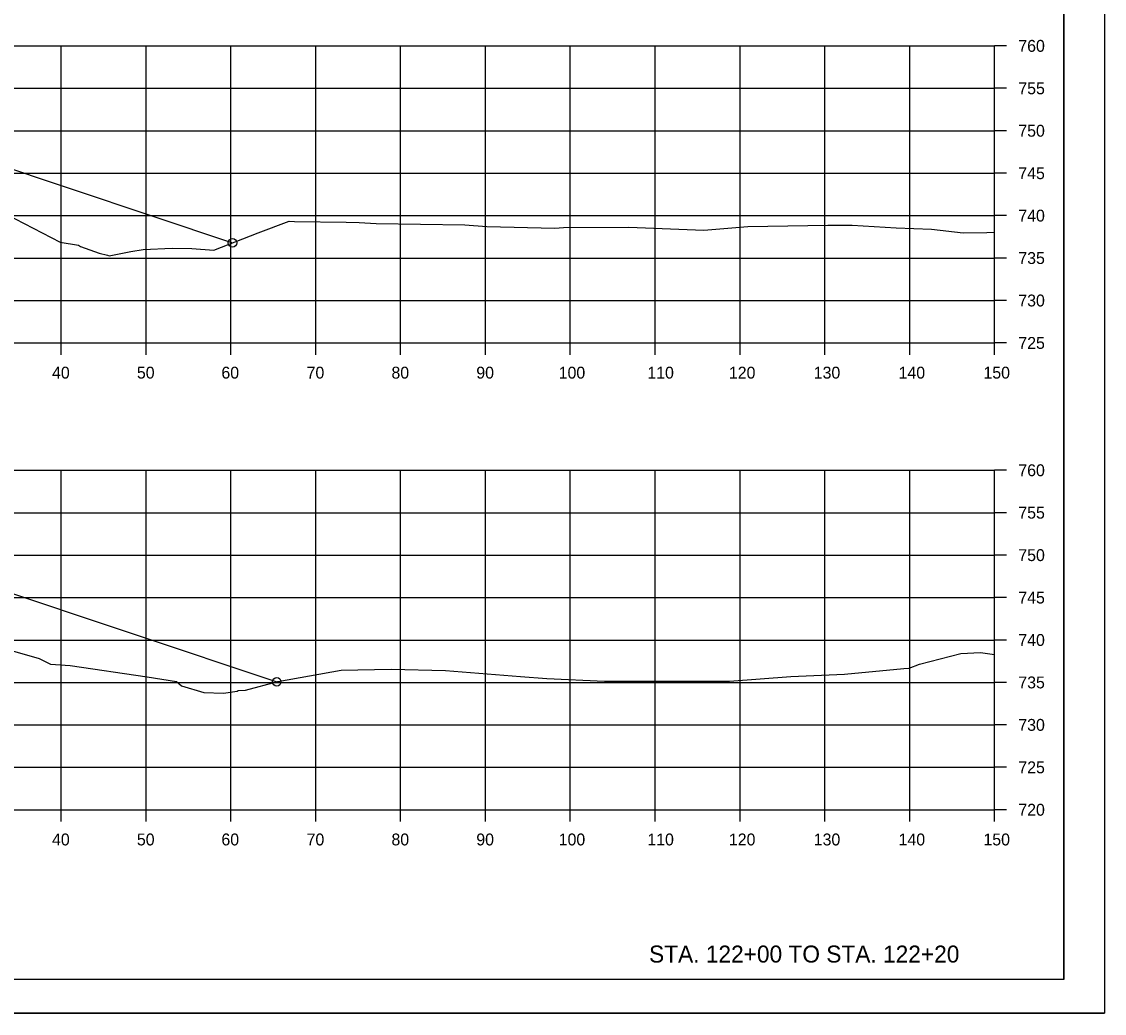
# Model space of a CAD drawing. Extents: x 1202951 to 1376887, y 378065 to 728038.
# Drawn here: x 1373132.5 to 1373260.1, y 381162.4 to 381279.3 of the extents above; entities that cross this region are included whole.
import ezdxf

# ---------------------------------------------------------------- set-up
doc = ezdxf.new("R2010")
doc.units = 0
for name, color, linetype in [('R_Axis', 7, 'Continuous'), ('R_Axis Annot', 7, 'Continuous'), ('R_Draft', 7, 'Continuous'), ('R_Exist Surface', 7, 'Continuous'), ('R_Grid', 7, 'Continuous'), ('R_No Plot', 7, 'Continuous')]:
    doc.layers.add(name, color=color, linetype=linetype)

msp = doc.modelspace()

# ---------------------------------------------------------------- linework, layer by layer
at = {"layer": 'R_Axis'}
for p, q in [((1373247.13, 381241.42), (1373247.13, 381276.42)), ((1373248.53, 381276.42), (1373247.13, 381276.42)), ((1373248.53, 381271.42), (1373247.13, 381271.42)), ((1373248.53, 381266.42), (1373247.13, 381266.42)), ((1373248.53, 381261.42), (1373247.13, 381261.42)), ((1373248.53, 381256.42), (1373247.13, 381256.42)), ((1373248.53, 381251.42), (1373247.13, 381251.42)), ((1373248.53, 381246.42), (1373247.13, 381246.42)), ((1372947.13, 381241.42), (1373247.13, 381241.42)), ((1373137.13, 381240.02), (1373137.13, 381241.42)), ((1373147.13, 381240.02), (1373147.13, 381241.42)), ((1373157.13, 381240.02), (1373157.13, 381241.42)), ((1373167.13, 381240.02), (1373167.13, 381241.42)), ((1373177.13, 381240.02), (1373177.13, 381241.42)), ((1373187.13, 381240.02), (1373187.13, 381241.42)), ((1373197.13, 381240.02), (1373197.13, 381241.42)), ((1373207.13, 381240.02), (1373207.13, 381241.42)), ((1373217.13, 381240.02), (1373217.13, 381241.42)), ((1373227.13, 381240.02), (1373227.13, 381241.42)), ((1373237.13, 381240.02), (1373237.13, 381241.42)), ((1373247.13, 381240.02), (1373247.13, 381241.42)), ((1373248.53, 381241.42), (1373247.13, 381241.42)), ((1373247.13, 381186.42), (1373247.13, 381226.42)), ((1373248.53, 381226.42), (1373247.13, 381226.42)), ((1373248.53, 381221.42), (1373247.13, 381221.42)), ((1373248.53, 381216.42), (1373247.13, 381216.42)), ((1373248.53, 381211.42), (1373247.13, 381211.42)), ((1373248.53, 381206.42), (1373247.13, 381206.42)), ((1373248.53, 381201.42), (1373247.13, 381201.42)), ((1373248.53, 381196.42), (1373247.13, 381196.42)), ((1373248.53, 381191.42), (1373247.13, 381191.42)), ((1372947.13, 381186.42), (1373247.13, 381186.42)), ((1373137.13, 381185.02), (1373137.13, 381186.42)), ((1373147.13, 381185.02), (1373147.13, 381186.42)), ((1373157.13, 381185.02), (1373157.13, 381186.42)), ((1373167.13, 381185.02), (1373167.13, 381186.42)), ((1373177.13, 381185.02), (1373177.13, 381186.42)), ((1373187.13, 381185.02), (1373187.13, 381186.42)), ((1373197.13, 381185.02), (1373197.13, 381186.42)), ((1373207.13, 381185.02), (1373207.13, 381186.42)), ((1373217.13, 381185.02), (1373217.13, 381186.42)), ((1373227.13, 381185.02), (1373227.13, 381186.42)), ((1373237.13, 381185.02), (1373237.13, 381186.42)), ((1373247.13, 381185.02), (1373247.13, 381186.42)), ((1373248.53, 381186.42), (1373247.13, 381186.42))]:
    msp.add_line(p, q, dxfattribs=at)
at = {"layer": 'R_Exist Surface'}
for points in [[(1373039.09, 381253.94), (1373065.63, 381262.78), (1373070.63, 381262.68), (1373073.63, 381262.62), (1373074.12, 381262.62), (1373074.13, 381262.12), (1373075.13, 381262.14), (1373097.13, 381262.58), (1373119.13, 381262.14), (1373120.13, 381262.12), (1373120.14, 381262.62), (1373120.63, 381262.62), (1373123.63, 381262.68), (1373128.63, 381262.78), (1373157.32, 381253.22)], [(1373130.65, 381256.61), (1373137, 381253.3), (1373139.17, 381252.92), (1373139.42, 381252.8), (1373141.59, 381251.98), (1373142.57, 381251.75), (1373142.77, 381251.68), (1373145.32, 381252.2), (1373146.78, 381252.42), (1373150.21, 381252.58), (1373152.54, 381252.55), (1373155.12, 381252.35), (1373160.33, 381254.4), (1373163.98, 381255.76), (1373164.64, 381255.71), (1373170.73, 381255.63), (1373172.23, 381255.61), (1373174.26, 381255.49), (1373184.68, 381255.33), (1373187.29, 381255.15), (1373195.3, 381254.96), (1373196.31, 381255.02), (1373204.02, 381255.06), (1373212.85, 381254.69), (1373218.05, 381255.12), (1373227.47, 381255.29), (1373229.07, 381255.3), (1373230.33, 381255.3), (1373235.53, 381254.98), (1373239.7, 381254.84), (1373243.42, 381254.41), (1373246.21, 381254.44), (1373247.13, 381254.46)], [(1373038.68, 381203.8), (1373065.63, 381212.79), (1373070.63, 381212.69), (1373073.63, 381212.63), (1373074.12, 381212.63), (1373074.13, 381212.13), (1373075.13, 381212.15), (1373097.13, 381212.59), (1373119.13, 381212.15), (1373120.13, 381212.13), (1373120.14, 381212.63), (1373120.63, 381212.63), (1373123.63, 381212.69), (1373128.63, 381212.79), (1373162.53, 381201.49)], [(1373131.1, 381205.21), (1373134.52, 381204.26), (1373135.87, 381203.58), (1373138.2, 381203.41), (1373147.27, 381202.08), (1373150.73, 381201.53), (1373151.3, 381201.03), (1373153.93, 381200.22), (1373156.24, 381200.14), (1373157.85, 381200.39), (1373157.99, 381200.46), (1373158.84, 381200.52), (1373162.67, 381201.52), (1373170.12, 381202.86), (1373176.02, 381203), (1373182.43, 381202.82), (1373191.24, 381202.11), (1373194.36, 381201.87), (1373201.14, 381201.59), (1373215.88, 381201.58), (1373223.12, 381202.11), (1373229.44, 381202.38), (1373236.45, 381203.06), (1373237.07, 381203.12), (1373238.29, 381203.56), (1373243.14, 381204.82), (1373245.46, 381204.94), (1373247.13, 381204.71)]]:
    msp.add_lwpolyline(points, dxfattribs=at)
at = {"layer": 'R_Grid'}
for p, q in [((1372947.13, 381276.42), (1373247.13, 381276.42)), ((1373137.13, 381241.42), (1373137.13, 381276.42)), ((1373147.13, 381241.42), (1373147.13, 381276.42)), ((1373157.13, 381241.42), (1373157.13, 381276.42)), ((1373167.13, 381241.42), (1373167.13, 381276.42)), ((1373177.13, 381241.42), (1373177.13, 381276.42)), ((1373187.13, 381241.42), (1373187.13, 381276.42)), ((1373197.13, 381241.42), (1373197.13, 381276.42)), ((1373207.13, 381241.42), (1373207.13, 381276.42)), ((1373217.13, 381241.42), (1373217.13, 381276.42)), ((1373227.13, 381241.42), (1373227.13, 381276.42)), ((1373237.13, 381241.42), (1373237.13, 381276.42)), ((1373247.13, 381241.42), (1373247.13, 381276.42)), ((1372947.13, 381271.42), (1373247.13, 381271.42)), ((1372947.13, 381266.42), (1373247.13, 381266.42)), ((1372947.13, 381261.42), (1373247.13, 381261.42)), ((1372947.13, 381256.42), (1373247.13, 381256.42)), ((1372947.13, 381251.42), (1373247.13, 381251.42)), ((1372947.13, 381246.42), (1373247.13, 381246.42)), ((1372947.13, 381241.42), (1373247.13, 381241.42)), ((1372947.13, 381226.42), (1373247.13, 381226.42)), ((1373137.13, 381186.42), (1373137.13, 381226.42)), ((1373147.13, 381186.42), (1373147.13, 381226.42)), ((1373157.13, 381186.42), (1373157.13, 381226.42)), ((1373167.13, 381186.42), (1373167.13, 381226.42)), ((1373177.13, 381186.42), (1373177.13, 381226.42)), ((1373187.13, 381186.42), (1373187.13, 381226.42)), ((1373197.13, 381186.42), (1373197.13, 381226.42)), ((1373207.13, 381186.42), (1373207.13, 381226.42)), ((1373217.13, 381186.42), (1373217.13, 381226.42)), ((1373227.13, 381186.42), (1373227.13, 381226.42)), ((1373237.13, 381186.42), (1373237.13, 381226.42)), ((1373247.13, 381186.42), (1373247.13, 381226.42)), ((1372947.13, 381221.42), (1373247.13, 381221.42)), ((1372947.13, 381216.42), (1373247.13, 381216.42)), ((1372947.13, 381211.42), (1373247.13, 381211.42)), ((1372947.13, 381206.42), (1373247.13, 381206.42)), ((1372947.13, 381201.42), (1373247.13, 381201.42)), ((1372947.13, 381196.42), (1373247.13, 381196.42)), ((1372947.13, 381191.42), (1373247.13, 381191.42)), ((1372947.13, 381186.42), (1373247.13, 381186.42))]:
    msp.add_line(p, q, dxfattribs=at)
at = {"layer": 'R_No Plot'}
for p, q in [((1373255.31, 381166.42), (1373255.31, 381371.88)), ((1373255.31, 381166.42), (1372939.13, 381166.42)), ((1372926.73, 381162.44), (1373260.07, 381162.44))]:
    msp.add_line(p, q, dxfattribs=at)
for points in [[(1372926.73, 381375.77), (1373260.07, 381375.77), (1373260.07, 381162.44), (1372926.73, 381162.44)], [(1373173.05, 381371.88), (1373192.67, 381371.88), (1373192.67, 381362), (1373208.79, 381362), (1373231.99, 381362), (1373231.99, 381337.67), (1373255.31, 381337.67), (1373255.31, 381166.42), (1372939.13, 381166.42), (1372939.13, 381371.88)]]:
    msp.add_lwpolyline(points, close=True, dxfattribs=at)
for centre in [(1373157.32, 381253.22), (1373162.53, 381201.49)]:
    msp.add_circle(centre, 0.5, dxfattribs=at)

# ---------------------------------------------------------------- texts
at = {"layer": 'R_Axis Annot'}
for s, p in [('760', (1373249.93, 381275.72)), ('755', (1373249.93, 381270.72)), ('750', (1373249.93, 381265.72)), ('745', (1373249.93, 381260.72)), ('740', (1373249.93, 381255.72)), ('735', (1373249.93, 381250.72)), ('730', (1373249.93, 381245.72)), ('725', (1373249.93, 381240.72)), ('40', (1373136.05, 381237.22)), ('50', (1373146.05, 381237.22)), ('60', (1373156.01, 381237.22)), ('70', (1373166.05, 381237.22)), ('80', (1373176.05, 381237.22)), ('90', (1373186.05, 381237.22)), ('100', (1373195.76, 381237.22)), ('110', (1373206.21, 381237.22)), ('120', (1373215.82, 381237.22)), ('130', (1373225.82, 381237.22)), ('140', (1373235.82, 381237.22)), ('150', (1373245.82, 381237.22)), ('760', (1373249.93, 381225.72)), ('755', (1373249.93, 381220.72)), ('750', (1373249.93, 381215.72)), ('745', (1373249.93, 381210.72)), ('740', (1373249.93, 381205.72)), ('735', (1373249.93, 381200.72)), ('730', (1373249.93, 381195.72)), ('725', (1373249.93, 381190.72)), ('720', (1373249.93, 381185.72)), ('40', (1373136.05, 381182.22)), ('50', (1373146.05, 381182.22)), ('60', (1373156.01, 381182.22)), ('70', (1373166.05, 381182.22)), ('80', (1373176.05, 381182.22)), ('90', (1373186.05, 381182.22)), ('100', (1373195.76, 381182.22)), ('110', (1373206.21, 381182.22)), ('120', (1373215.82, 381182.22)), ('130', (1373225.82, 381182.22)), ('140', (1373235.82, 381182.22)), ('150', (1373245.82, 381182.22))]:
    msp.add_text(s, height=1.4, dxfattribs=at).set_placement(p)
at = {"layer": 'R_Draft'}
msp.add_text('STA. 122+00 TO STA. 122+20', height=2, dxfattribs=at).set_placement((1373206.41, 381168.42))

doc.saveas('drawing.dxf')
